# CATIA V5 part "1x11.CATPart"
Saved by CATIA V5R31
Part number: 1x11
Definition: 11M Beam 4603472/64290
Nomenclature: 11M Beam 4603472/64290
Source: Unknown
Bounding box of the stored display mesh (mm): x -0.1 to 7.102, y -3.6 to 83.6, z 0 to 8
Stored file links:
  C:\Users\super\Desktop\LEGO\TFG-2621\TFG_02621_anejos\1x11.CATPart
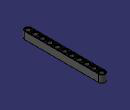
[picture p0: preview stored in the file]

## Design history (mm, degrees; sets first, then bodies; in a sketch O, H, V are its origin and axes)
AxisSystem1: origin (0, 0, 0), X (1, 0, 0), Y (0, 1, 0), Z (0, 0, 1)
Body1 "Body1" (main body)
  Solid1: solid without history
